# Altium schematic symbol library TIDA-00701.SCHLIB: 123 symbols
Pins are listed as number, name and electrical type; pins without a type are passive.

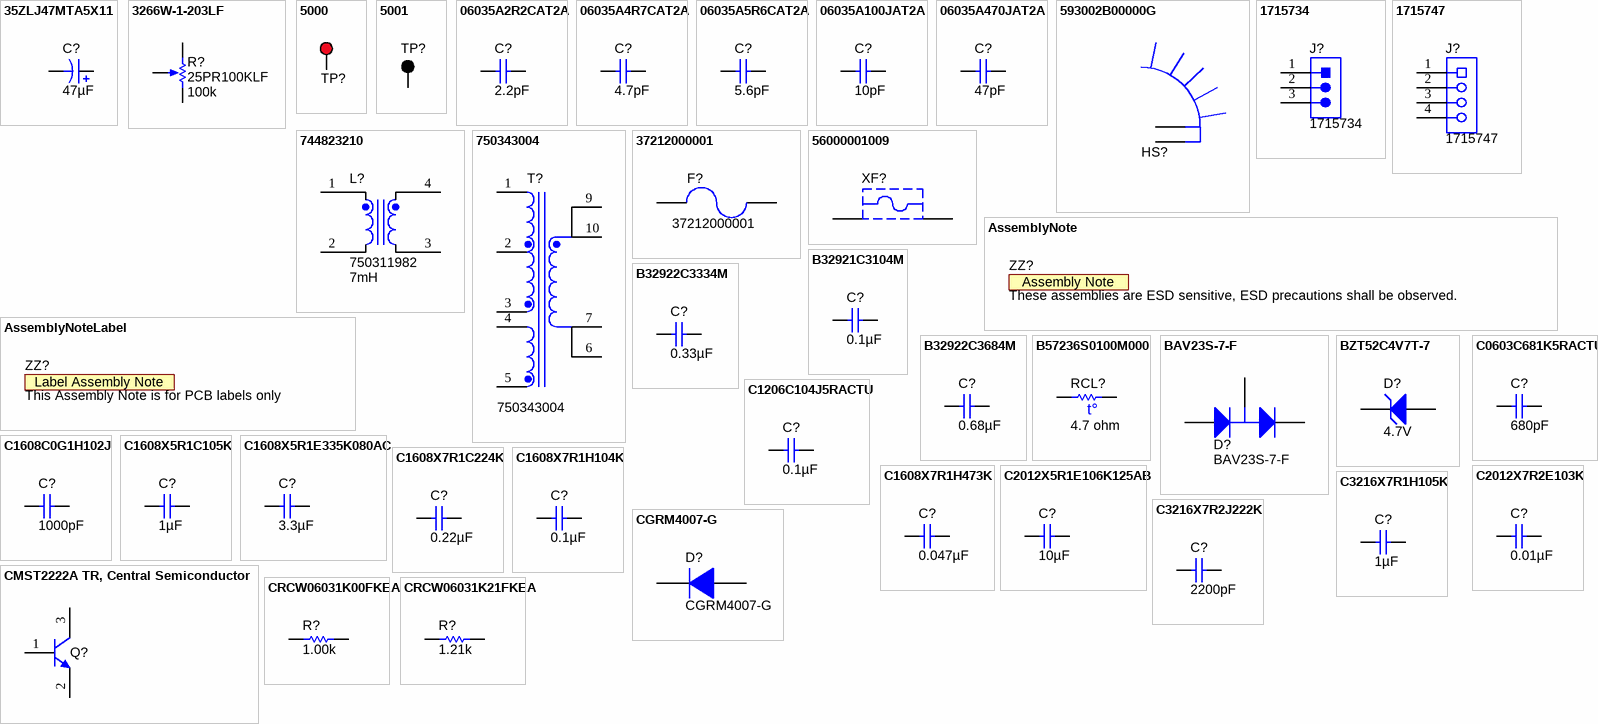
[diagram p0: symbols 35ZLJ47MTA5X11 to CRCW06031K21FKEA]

## 35ZLJ47MTA5X11
designator C?  ValueDisplayed: 47µF  (hidden comment: 35ZLJ47MTA5X11)
CAP, AL, 47 µF, 35 V, +/- 20%, 0.4 ohm, TH; Manufacturer: Rubycon; Polarized: Y; CompType: Capacitor; Value: 47uF; U/M: EA; Cap_F: 0.000047; Tolerance_%: 20; ESR_ohm: 0.4; Value1: 0.4 ohm; VDC_V: 35; Value2: 35V; IRMS_A: 0.45; TaMin_C: -40; TaMax_C: 105; Cap_Case: 5x11mm
signal-integrity model Cap
simulation model Cap
footprint ZLJ_500x1100 (TH, 2-Leads, Dia 5mm,  Lead Spacing 2mm)
pins: 1 +, 2 -

## 3266W-1-203LF
designator R?, comment 25PR100KLF  value 100k
TRIMMER 100K OHM 0.5W TH; Manufacturer: TT Electronics/BI; Sim Note: Enter the Resistance value and the set point into parameter fields.
simulation model POT (Potentiometer)
footprint TRIM_3266W
footprint POT_25PXXXXXX (Potentiometer, 25p series, through hole, 3 pin)
pins: 1 CCW, 2 WIPER, 3 CW
1 alternate drawing of the same symbol

## 5000
designator TP?  (value not drawn)
Test Point, Miniature, Red, TH; Manufacturer: Keystone; CompType: Test Point Loop; U/M: EA
footprint Keystone5000 (For Keystone 500x miniature loop terminals)
pins: 1

## 5001
designator TP?  (value not drawn)
Test Point, Miniature, Black, TH; Manufacturer: Keystone; CompType: Test Point Loop; U/M: EA
footprint Keystone5001 (For Keystone 500x miniature loop terminals)
pins: 1

## 06035A2R2CAT2A
designator C?  ValueDisplayed: 2.2pF  (hidden comment: 06035A2R2CAT2A)
CAP, CERM, 2.2 pF, 50 V, +/- 11%, C0G/NP0, 0603; Manufacturer: AVX; Polarized: N; CompType: Capacitor; Value: 2.2pF; U/M: EA; Cap_F: 0.0000000000022; Tolerance_%: 11; ESR_ohm: 1.033; Value1: 1.033 ohm; VDC_V: 50; Value2: 50V; TaMin_C: -55; TaMax_C: 125; Cap_Case: 0603
signal-integrity model Cap
simulation model Cap
footprint 0603
footprint 0603M
footprint 0603L
footprint 0603_HV
footprint 0603S
pins: 1, 2

## 06035A4R7CAT2A
designator C?  ValueDisplayed: 4.7pF  (hidden comment: 06035A4R7CAT2A)
CAP, CERM, 4.7 pF, 50 V, +/- 5%, C0G/NP0, 0603; Manufacturer: AVX; Polarized: N; CompType: Capacitor; Value: 4.7pF; U/M: EA; Cap_F: 0.0000000000047; Tolerance_%: 5; ESR_ohm: 0.633; Value1: 0.633 ohm; VDC_V: 50; Value2: 50V; TaMin_C: -55; TaMax_C: 125; Cap_Case: 0603
signal-integrity model Cap
simulation model Cap
footprint 0603
footprint 0603M
footprint 0603L
footprint 0603_HV
footprint 0603S
pins: 1, 2

## 06035A5R6CAT2A
designator C?  ValueDisplayed: 5.6pF  (hidden comment: 06035A5R6CAT2A)
CAP, CERM, 5.6 pF, 50 V, +/- 5%, C0G/NP0, 0603; Manufacturer: AVX; Polarized: N; CompType: Capacitor; Value: 5.6pF; U/M: EA; Cap_F: 0.0000000000056; Tolerance_%: 5; ESR_ohm: 0.568; Value1: 0.568 ohm; VDC_V: 50; Value2: 50V; TaMin_C: -55; TaMax_C: 125; Cap_Case: 0603
signal-integrity model Cap
simulation model Cap
footprint 0603
footprint 0603M
footprint 0603L
footprint 0603_HV
footprint 0603S
pins: 1, 2

## 06035A100JAT2A
designator C?  ValueDisplayed: 10pF  (hidden comment: 06035A100JAT2A)
CAP, CERM, 10 pF, 50 V, +/- 5%, C0G/NP0, 0603; Manufacturer: AVX; Polarized: N; CompType: Capacitor; Value: 10pF; U/M: EA; Cap_F: 0.00000000001; Tolerance_%: 5; ESR_ohm: 0.403; Value1: 0.403 ohm; VDC_V: 50; Value2: 50V; TaMin_C: -55; TaMax_C: 125; Cap_Case: 0603
signal-integrity model Cap
simulation model Cap
footprint 0603
footprint 0603M
footprint 0603L
footprint 0603_HV
footprint 0603S
pins: 1, 2

## 06035A470JAT2A
designator C?  ValueDisplayed: 47pF  (hidden comment: 06035A470JAT2A)
CAP, CERM, 47 pF, 50 V, +/- 5%, C0G/NP0, 0603; Manufacturer: AVX; Polarized: N; CompType: Capacitor; Value: 47pF; U/M: EA; Cap_F: 0.000000000047; Tolerance_%: 5; ESR_ohm: 0.174; Value1: 0.174 ohm; VDC_V: 50; Value2: 50V; TaMin_C: -55; TaMax_C: 125; Cap_Case: 0603
signal-integrity model Cap
simulation model Cap
footprint 0603
footprint 0603M
footprint 0603L
footprint 0603_HV
footprint 0603S
pins: 1, 2

## 593002B00000G
designator HS?  (value not drawn)
HEATSINK TWISTED FIN TO-220 Vertical; Manufacturer: Aavid Thermalloy; SymbolCreator: a0799628; Value: 13.4°C/W
footprint HSINK_593002B00000G (Heat Sink, TO-220 Vertical)
footprint HEATSINK_593002B03400G (HEATSINK, 25X12.7X29.97 MM)
pins: 1, 2

## 1715734
designator J?
TERM BLOCK 3POS 5.08MM, TH; Manufacturer: Phoenix Contact; SymbolCreator: a0799628; CompType: Header; U/M: EA
footprint Phoenix_1715734 (Phoenix)
pins: 1, 2, 3
3 alternate drawings of the same symbol

## 1715747
designator J?
Terminal Block, 5.08mm, 4x1, TH; Manufacturer: Phoenix Contact; SymbolCreator: a0411947; U/M: EA
footprint Phoenix_1715747 (Terminal Block, 5.08mm, 4x1, TH)
pins: 1, 2, 3, 4

## 744823210
designator L?, comment 750311982  ValueDisplayed: 7mH
Coupled inductor, 7mH, 2 A, 0.045 ohm, 3.7-7.1 mH; Manufacturer: Wurth Elektronik; SymbolCreator: a0412235; Value: 3.7-7.3mH; Ind_H: 7e-3; DCR_ohm: 0.045; Isat: 2; Tolerance_%: 30
footprint 750311982 (4 LEAD,TH)
pins: 1, 2, 3, 4

## 750343004
designator T?
TRANSFORMER, 160.0uH, 10%, TH-10PIN; Manufacturer: WURTH ELEKTRONIK; SymbolCreator: x0199378
footprint INDRD900W80D1170H1300 (INDUCTOR, 0.8MM LEAD DIA, PITCH 9MM)
footprint WE_75034300X (TRANS OR IND, PITCH 5MM, 29.84X24X33MM, TH-10PIN)
pins: 1, 2, 3, 4, 5, 6, 7, 9, 10

## 37212000001
designator F?
Fuse, 2 A, 250 V, TH; Manufacturer: Littelfuse; U/M: EA; OpeningTime_200%_max: 2; VDC_V: 250; Vdrop: 0.085; Soldering_Wave_MaxTemp_C: 260; Soldering_Wave_MaxTime_s: 5
footprint FUSE_372 (LITTELFUSE)
pins: 1, 2

## 56000001009
designator XF?  (value not drawn)
FUSE HOLDER RADIAL 250V 6.3A PCB; Manufacturer: Littelfuse; SymbolCreator: a0412235; Value: TR5
footprint FuseHolder_560000010 (Littelfuse fuse holder TR5)
pins: 1, 2

## AssemblyNote
designator ZZ?, comment These assemblies are ESD sensitive, ESD precautions shall be observed.  (no BOM)
SymbolCreator: codlsc; CompType: AssemblyNote
footprint AssemblyNote

## AssemblyNoteLabel
designator ZZ?, comment This Assembly Note is for PCB labels only  (no BOM)
SymbolCreator: a0412235
footprint AssemblyNoteLabel

## B32921C3104M
designator C?  ValueDisplayed: 0.1µF  (hidden comment: B32921C3104M)
CAP, Film, 0.1 µF, 305 V, +/- 20%, TH; Manufacturer: TDK; Polarized: N; CompType: Capacitor; Value: 0.1uF; U/M: EA; Cap_F: 0.0000001; Tolerance_%: 20; Value1: Unknown; VDC_V: 305; Value2: 305V; TaMin_C: -40; TaMax_C: 110; Cap_Case: 13x12x6mm
signal-integrity model Cap
simulation model Cap
footprint B32921_1300x1200x600 (EPCOS)
pins: 1, 2

## B32922C3334M
designator C?  ValueDisplayed: 0.33µF  (hidden comment: B32922C3334M)
CAP, Film, 0.33 µF, 630 V, +/- 20%, TH; Manufacturer: TDK; Polarized: N; CompType: Capacitor; Value: 0.33uF; U/M: EA; Cap_F: 0.00000033; Tolerance_%: 20; Value1: Unknown; VDC_V: 630; Value2: 630V; TaMax_C: 110; AEC Category: Q200
signal-integrity model Cap
simulation model Cap
footprint B32922_14.5mm
pins: 1, 2

## B32922C3684M
designator C?  ValueDisplayed: 0.68µF  (hidden comment: B32922C3684M)
CAP, Film, 0.68 µF, 630 V, +/- 20%, TH; Manufacturer: TDK; Polarized: N; CompType: Capacitor; Value: 0.68uF; U/M: EA; Cap_F: 0.00000068; Tolerance_%: 20; Value1: Unknown; VDC_V: 630; Value2: 630V; TaMax_C: 110
signal-integrity model Cap
simulation model Cap
footprint B32922_18.5mm
pins: 1, 2

## B57236S0100M000
designator RCL?, comment value 4.7 ohm  (hidden comment: B57236S479M)
ICL 4.7 OHM 20% 4.6A 11.51MM; Manufacturer: TDK; CompType: ThermistorNTC; Tolerance_%: 20; Power_W: 2.1; U/M: EA; TaMin_C: -55; TaMax_C: 170
footprint THERM_B57236S0 (EPCOS)
pins: 1, 2

## BAV23S-7-F
designator D?
Diode, Switching, 200 V, 0.4 A, SOT-23; Manufacturer: Diodes Inc.; U/M: EA; Vf_V: 1.25; Value: 200V; Value1: 0.4A; Value2: 1.25V; Io_A: 0.4; Vr_V: 200; TJmax_C: 150; RJC_CperW: 357
footprint SOT-23 (SOT23, 3-Leads, Body 2.9x1.3mm, Pitch 0.95mm, Lead Span 2.5mm, IPC Medium Density)
footprint SOT-23M
footprint SOT-23L
pins: 1 A, 2 K, 3 C
1 alternate drawing of the same symbol

## BZT52C4V7T-7
designator D?  value 4.7V  (hidden comment: BZT52C4V7T-7)
Diode, Zener, 4.7 V, 300 mW, SOD-523; Manufacturer: Diodes Inc.; U/M: EA; SymbolCreator: a0412235; Power_W: 0.3; Vz_V: 4.7; Value1: 0.3W; RJA_CperW: 417
signal-integrity model Diode
footprint SOD-523
pins: 1 K, 2 A

## C0603C681K5RACTU
designator C?  ValueDisplayed: 680pF  (hidden comment: C0603C681K5RACTU)
CAP, CERM, 680 pF, 50 V, +/- 10%, X7R, 0603; Manufacturer: Kemet; Polarized: N; CompType: Capacitor; Value: 680pF; U/M: EA; Cap_F: 0.00000000068; Tolerance_%: 10; Value1: Unknown; VDC_V: 50; Value2: 50V; TaMin_C: -55; TaMax_C: 125; Cap_Case: 0603
signal-integrity model Cap
simulation model Cap
footprint 0603
footprint 0603M
footprint 0603L
footprint 0603_HV
footprint 0603S
pins: 1, 2

## C1206C104J5RACTU
designator C?  ValueDisplayed: 0.1µF  (hidden comment: C1206C104J5RACTU)
CAP, CERM, 0.1 µF, 50 V, +/- 5%, X7R, 1206; Manufacturer: Kemet; Polarized: N; CompType: Capacitor; Value: 0.1uF; U/M: EA; Cap_F: 0.0000001; Tolerance_%: 5; ESR_ohm: 0.059; Value1: 0.059 ohm; VDC_V: 50; Value2: 50V; IRMS_A: 1.2; TaMin_C: -55; TaMax_C: 125; Cap_Case: 1206
signal-integrity model Cap
simulation model Cap
footprint 1206
footprint 1206M
footprint 1206L
pins: 1, 2

## C1608C0G1H102J
designator C?  ValueDisplayed: 1000pF  (hidden comment: C1608C0G1H102J)
CAP, CERM, 1000 pF, 50 V, +/- 5%, C0G/NP0, 0603; Manufacturer: TDK; Polarized: N; CompType: Capacitor; Value: 1000pF; U/M: EA; Cap_F: 0.000000001; Tolerance_%: 5; ESR_ohm: 0.0563; Value1: 0.0563 ohm; VDC_V: 50; Value2: 50V; TaMin_C: -55; TaMax_C: 125; Cap_Case: 0603
signal-integrity model Cap
simulation model Cap
footprint 0603
footprint 0603M
footprint 0603L
footprint 0603_HV
footprint 0603S
pins: 1, 2

## C1608X5R1C105K
designator C?  ValueDisplayed: 1µF  (hidden comment: C1608X5R1C105K)
CAP, CERM, 1 µF, 16 V, +/- 10%, X5R, 0603; Manufacturer: TDK; Polarized: N; CompType: Capacitor; Value: 1uF; U/M: EA; Cap_F: 0.000001; Tolerance_%: 10; ESR_ohm: 0.0057; Value1: 0.0057 ohm; VDC_V: 16; Value2: 16V; TaMin_C: -55; TaMax_C: 85; Cap_Case: 0603; AEC Category: Q200
signal-integrity model Cap
simulation model Cap
footprint 0603
footprint 0603M
footprint 0603L
footprint 0603_HV
footprint 0603S
pins: 1, 2

## C1608X5R1E335K080AC
designator C?  ValueDisplayed: 3.3µF  (hidden comment: C1608X5R1E335K080AC)
CAP, CERM, 3.3 µF, 25 V, +/- 10%, X5R, 0603; Manufacturer: TDK; Polarized: N; CompType: Capacitor; Value: 3.3uF; U/M: EA; Cap_F: 0.0000033; Tolerance_%: 10; Value1: Unknown; VDC_V: 25; Value2: 25V; TaMin_C: -55; TaMax_C: 85; Cap_Case: 0603
signal-integrity model Cap
simulation model Cap
footprint 0603
footprint 0603M
footprint 0603L
footprint 0603_HV
footprint 0603S
pins: 1, 2

## C1608X7R1C224K
designator C?  ValueDisplayed: 0.22µF  (hidden comment: C1608X7R1C224K)
CAP, CERM, 0.22 µF, 16 V, +/- 10%, X7R, 0603; Manufacturer: TDK; Polarized: N; CompType: Capacitor; Value: 0.22uF; U/M: EA; Cap_F: 0.00000022; Tolerance_%: 10; ESR_ohm: 0.0125; Value1: 0.0125 ohm; VDC_V: 16; Value2: 16V; TaMin_C: -55; TaMax_C: 125; Cap_Case: 0603
signal-integrity model Cap
simulation model Cap
footprint 0603
footprint 0603M
footprint 0603L
footprint 0603_HV
footprint 0603S
pins: 1, 2

## C1608X7R1H104K
designator C?  ValueDisplayed: 0.1µF  (hidden comment: C1608X7R1H104K)
CAP, CERM, 0.1 µF, 50 V, +/- 10%, X7R, 0603; Manufacturer: TDK; Polarized: N; CompType: Capacitor; Value: 0.1uF; U/M: EA; Cap_F: 0.0000001; Tolerance_%: 10; ESR_ohm: 0.017; Value1: 0.017 ohm; VDC_V: 50; Value2: 50V; TaMin_C: -55; TaMax_C: 125; Cap_Case: 0603
signal-integrity model Cap
simulation model Cap
footprint 0603
footprint 0603M
footprint 0603L
footprint 0603_HV
footprint 0603S
pins: 1, 2

## C1608X7R1H473K
designator C?  ValueDisplayed: 0.047µF  (hidden comment: C1608X7R1H473K)
CAP, CERM, 0.047 µF, 50 V, +/- 10%, X7R, 0603; Manufacturer: TDK; Polarized: N; CompType: Capacitor; Value: 0.047uF; U/M: EA; Cap_F: 0.000000047; Tolerance_%: 10; ESR_ohm: 0.0234; Value1: 0.0234 ohm; VDC_V: 50; Value2: 50V; TaMin_C: -55; TaMax_C: 125; Cap_Case: 0603
signal-integrity model Cap
simulation model Cap
footprint 0603
footprint 0603M
footprint 0603L
footprint 0603_HV
footprint 0603S
pins: 1, 2

## C2012X5R1E106K125AB
designator C?  ValueDisplayed: 10µF  (hidden comment: C2012X5R1E106K125AB)
CAP, CERM, 10 µF, 25 V, +/- 10%, X5R, 0805; Manufacturer: TDK; Polarized: N; CompType: Capacitor; Value: 10uF; U/M: EA; Cap_F: 0.00001; Tolerance_%: 10; Value1: Unknown; VDC_V: 25; Value2: 25V; TaMin_C: -55; TaMax_C: 85; Cap_Case: 0805
signal-integrity model Cap
simulation model Cap
footprint 0805_HV (0805 with 30mil clearance between pads)
footprint 0805
footprint 0805M
footprint 0805L
pins: 1, 2

## C2012X7R2E103K
designator C?  ValueDisplayed: 0.01µF  (hidden comment: C2012X7R2E103K)
CAP, CERM, 0.01 µF, 250 V, +/- 10%, X7R, 0805; Manufacturer: TDK; Polarized: N; CompType: Capacitor; Value: 0.01uF; U/M: EA; Cap_F: 0.00000001; Tolerance_%: 10; ESR_ohm: 0.0681; Value1: 0.0681 ohm; VDC_V: 250; Value2: 250V; TaMin_C: -55; TaMax_C: 125; Cap_Case: 0805
signal-integrity model Cap
simulation model Cap
footprint 0805_HV
footprint 0805
footprint 0805M
footprint 0805L
pins: 1, 2

## C3216X7R1H105K
designator C?  ValueDisplayed: 1µF  (hidden comment: C3216X7R1H105K)
CAP, CERM, 1 µF, 50 V, +/- 10%, X7R, 1206; Manufacturer: TDK; Polarized: N; CompType: Capacitor; Value: 1uF; U/M: EA; Cap_F: 0.000001; Tolerance_%: 10; ESR_ohm: 0.01; Value1: 0.01 ohm; VDC_V: 50; Value2: 50V; IRMS_A: 3.2; TaMin_C: -55; TaMax_C: 125; Cap_Case: 1206
signal-integrity model Cap
simulation model Cap
footprint 1206
footprint 1206M
footprint 1206L
pins: 1, 2

## C3216X7R2J222K
designator C?  ValueDisplayed: 2200pF  (hidden comment: C3216X7R2J222K)
CAP, CERM, 2200 pF, 630 V, +/- 10%, X7R, 1206; Manufacturer: TDK; Polarized: N; CompType: Capacitor; Value: 2200pF; U/M: EA; Cap_F: 0.0000000022; Tolerance_%: 10; ESR_ohm: 0.151; Value1: 0.151 ohm; VDC_V: 630; Value2: 630V; TaMin_C: -55; TaMax_C: 125; Cap_Case: 1206; AEC Category: Q200
signal-integrity model Cap
simulation model Cap
footprint 1206
footprint 1206M
footprint 1206L
pins: 1, 2

## CGRM4007-G
designator D?
Diode, P-N, 1000 V, 1 A, 3.9x1.7x1.8mm; Manufacturer: Comchip Technology; U/M: EA; Vf_V: 1.1; Value: 1000V; Value1: 1A; Value2: 1.1V; Io_A: 1; Vr_V: 1000; TJmax_C: 150
signal-integrity model Diode
footprint MINI-SMA
pins: 1 K, 2 A

## CMST2222A TR, Central Semiconductor
designator Q?, comment MMBT4401WT1G  (value not drawn)
Transistor, NPN, 40 V, 0.6 A, SOT-323; Manufacturer: ON Semiconductor; CompType: BJT; PNP: 0; NPN: 1; Vceo_V: 40; Vcesat1_V: 0.3; Value: 40 V; IcRated_A: 0.6; Value1: 0.6 A; TaMin_C: -65; TaMax_C: 150; U/M: EA
footprint SOT-323 (Zetex recommended land pattern.  March 2007)
pins: 1 B, 2 E, 3 C

## CRCW06031K00FKEA
designator R?  ValueDisplayed: 1.00k  (hidden comment: CRCW06031K00FKEA)
RES, 1.00 k, 1%, 0.1 W, 0603; Manufacturer: Vishay-Dale; CompType: Resistor; Value: 1.00k; Res_ohm: 1000; Value_Code: 1k00; Tolerance_%: 1; Power_W: 0.1; Value2: 0.1W; VDC_V: 75; TempCo: 100 ppm/C; EIA_Code: E96; U/M: EA
signal-integrity model Resistor
simulation model Resistor
footprint 0603
footprint 0603M
footprint 0603L
footprint 0603_HV
footprint 0603S
pins: 1, 2

## CRCW06031K21FKEA
designator R?  ValueDisplayed: 1.21k  (hidden comment: CRCW06031K21FKEA)
RES, 1.21 k, 1%, 0.1 W, 0603; Manufacturer: Vishay-Dale; CompType: Resistor; Value: 1.21k; Res_ohm: 1210; Value_Code: 1k21; Tolerance_%: 1; Power_W: 0.1; Value2: 0.1W; VDC_V: 75; TempCo: 100 ppm/C; EIA_Code: E96; U/M: EA; AEC Category: Q200
signal-integrity model Resistor
simulation model Resistor
footprint 0603
footprint 0603M
footprint 0603L
footprint 0603_HV
footprint 0603S
pins: 1, 2

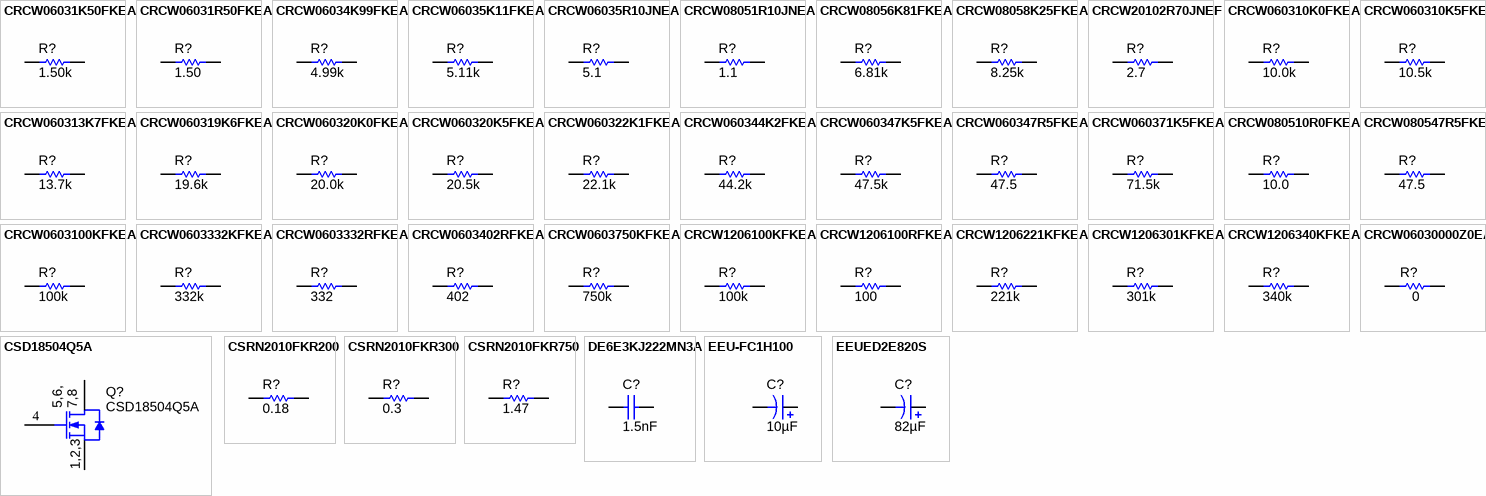
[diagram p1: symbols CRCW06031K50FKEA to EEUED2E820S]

## CRCW06031K50FKEA
designator R?  ValueDisplayed: 1.50k  (hidden comment: CRCW06031K50FKEA)
RES, 1.50 k, 1%, 0.1 W, 0603; Manufacturer: Vishay-Dale; CompType: Resistor; Value: 1.50k; Res_ohm: 1500; Value_Code: 1k50; Tolerance_%: 1; Power_W: 0.1; Value2: 0.1W; VDC_V: 75; TempCo: 100 ppm/C; EIA_Code: E96; U/M: EA
signal-integrity model Resistor
simulation model Resistor
footprint 0603
footprint 0603M
footprint 0603L
footprint 0603_HV
footprint 0603S
pins: 1, 2

## CRCW06031R50FKEA
designator R?  ValueDisplayed: 1.50  (hidden comment: CRCW06031R50FKEA)
RES, 1.50, 1%, 0.1 W, 0603; Manufacturer: Vishay-Dale; CompType: Resistor; Value: 1.50; Res_ohm: 1.5; Value_Code: 1R50; Tolerance_%: 1; Power_W: 0.1; Value2: 0.1W; VDC_V: 75; TempCo: 100 ppm/C; EIA_Code: E96; U/M: EA
signal-integrity model Resistor
simulation model Resistor
footprint 0603
footprint 0603M
footprint 0603L
footprint 0603_HV
footprint 0603S
pins: 1, 2

## CRCW06034K99FKEA
designator R?  ValueDisplayed: 4.99k  (hidden comment: CRCW06034K99FKEA)
RES, 4.99 k, 1%, 0.1 W, 0603; Manufacturer: Vishay-Dale; CompType: Resistor; Value: 4.99k; Res_ohm: 4990; Value_Code: 4k99; Tolerance_%: 1; Power_W: 0.1; Value2: 0.1W; VDC_V: 75; TempCo: 100 ppm/C; EIA_Code: E96; U/M: EA
signal-integrity model Resistor
simulation model Resistor
footprint 0603
footprint 0603M
footprint 0603L
footprint 0603_HV
footprint 0603S
pins: 1, 2

## CRCW06035K11FKEA
designator R?  ValueDisplayed: 5.11k  (hidden comment: CRCW06035K11FKEA)
RES, 5.11 k, 1%, 0.1 W, 0603; Manufacturer: Vishay-Dale; CompType: Resistor; Value: 5.11k; Res_ohm: 5110; Value_Code: 5k11; Tolerance_%: 1; Power_W: 0.1; Value2: 0.1W; VDC_V: 75; TempCo: 100 ppm/C; EIA_Code: E96; U/M: EA
signal-integrity model Resistor
simulation model Resistor
footprint 0603
footprint 0603M
footprint 0603L
footprint 0603_HV
footprint 0603S
pins: 1, 2

## CRCW06035R10JNEA
designator R?  ValueDisplayed: 5.1  (hidden comment: CRCW06035R10JNEA)
RES, 5.1, 5%, 0.1 W, 0603; Manufacturer: Vishay-Dale; CompType: Resistor; Value: 5.1; Value_Code: 5R10; Tolerance_%: 5; Power_W: 0.1; Value2: 0.1W; VDC_V: 75; TempCo: 200 ppm/C; EIA_Code: E24; U/M: EA; AEC Category: Q200
signal-integrity model Resistor
simulation model Resistor
footprint 0603
footprint 0603M
footprint 0603L
footprint 0603_HV
footprint 0603S
pins: 1, 2

## CRCW08051R10JNEA
designator R?  ValueDisplayed: 1.1  (hidden comment: CRCW08051R10JNEA)
RES, 1.1, 5%, 0.125 W, 0805; Manufacturer: Vishay-Dale; CompType: Resistor; Value: 1.1; Value_Code: 1R10; Tolerance_%: 5; Power_W: 0.125; Value2: 0.125W; VDC_V: 150; TempCo: 200 ppm/C; EIA_Code: E24; U/M: EA; AEC Category: Q200
signal-integrity model Resistor
simulation model Resistor
footprint 0805_HV
footprint 0805_HV1
footprint 0805
footprint 0805M
pins: 1, 2

## CRCW08056K81FKEA
designator R?  ValueDisplayed: 6.81k  (hidden comment: CRCW08056K81FKEA)
RES, 6.81 k, 1%, 0.125 W, 0805; Manufacturer: Vishay-Dale; CompType: Resistor; Value: 6.81k; Res_ohm: 6810; Value_Code: 6k81; Tolerance_%: 1; Power_W: 0.125; Value2: 0.125W; VDC_V: 150; TempCo: 100 ppm/C; EIA_Code: E96; U/M: EA; AEC Category: Q200
signal-integrity model Resistor
simulation model Resistor
footprint 0805_HV
footprint 0805_HV1
footprint 0805
footprint 0805M
pins: 1, 2

## CRCW08058K25FKEA
designator R?  ValueDisplayed: 8.25k  (hidden comment: CRCW08058K25FKEA)
RES, 8.25 k, 1%, 0.125 W, 0805; Manufacturer: Vishay-Dale; CompType: Resistor; Value: 8.25k; Res_ohm: 8250; Value_Code: 8k25; Tolerance_%: 1; Power_W: 0.125; Value2: 0.125W; VDC_V: 150; TempCo: 100 ppm/C; EIA_Code: E96; U/M: EA; AEC Category: Q200
signal-integrity model Resistor
simulation model Resistor
footprint 0805_HV
footprint 0805_HV1
footprint 0805
footprint 0805M
pins: 1, 2

## CRCW20102R70JNEF
designator R?  ValueDisplayed: 2.7  (hidden comment: CRCW20102R70JNEF)
RES, 2.7, 5%, 0.75 W, 2010; Manufacturer: Vishay-Dale; CompType: Resistor; Value: 2.7; Value_Code: 2R70; Tolerance_%: 5; Power_W: 0.75; Value2: 0.75W; VDC_V: 400; TempCo: 200 ppm/C; EIA_Code: E24; U/M: EA
signal-integrity model Resistor
simulation model Resistor
footprint 2010
footprint 2010M
footprint 2010L
pins: 1, 2

## CRCW060310K0FKEA
designator R?  ValueDisplayed: 10.0k  (hidden comment: CRCW060310K0FKEA)
RES, 10.0 k, 1%, 0.1 W, 0603; Manufacturer: Vishay-Dale; CompType: Resistor; Value: 10.0k; Res_ohm: 10000; Value_Code: 10k0; Tolerance_%: 1; Power_W: 0.1; Value2: 0.1W; VDC_V: 75; TempCo: 100 ppm/C; EIA_Code: E96; U/M: EA
signal-integrity model Resistor
simulation model Resistor
footprint 0603
footprint 0603M
footprint 0603L
footprint 0603_HV
footprint 0603S
pins: 1, 2

## CRCW060310K5FKEA
designator R?  ValueDisplayed: 10.5k  (hidden comment: CRCW060310K5FKEA)
RES, 10.5 k, 1%, 0.1 W, 0603; Manufacturer: Vishay-Dale; CompType: Resistor; Value: 10.5k; Res_ohm: 10500; Value_Code: 10k5; Tolerance_%: 1; Power_W: 0.1; Value2: 0.1W; VDC_V: 75; TempCo: 100 ppm/C; EIA_Code: E96; U/M: EA; AEC Category: Q200
signal-integrity model Resistor
simulation model Resistor
footprint 0603
footprint 0603M
footprint 0603L
footprint 0603_HV
footprint 0603S
pins: 1, 2

## CRCW060313K7FKEA
designator R?  ValueDisplayed: 13.7k  (hidden comment: CRCW060313K7FKEA)
RES, 13.7 k, 1%, 0.1 W, 0603; Manufacturer: Vishay-Dale; CompType: Resistor; Value: 13.7k; Res_ohm: 13700; Value_Code: 13k7; Tolerance_%: 1; Power_W: 0.1; Value2: 0.1W; VDC_V: 75; TempCo: 100 ppm/C; EIA_Code: E96; U/M: EA
signal-integrity model Resistor
simulation model Resistor
footprint 0603
footprint 0603M
footprint 0603L
footprint 0603_HV
footprint 0603S
pins: 1, 2

## CRCW060319K6FKEA
designator R?  ValueDisplayed: 19.6k  (hidden comment: CRCW060319K6FKEA)
RES, 19.6 k, 1%, 0.1 W, 0603; Manufacturer: Vishay-Dale; CompType: Resistor; Value: 19.6k; Res_ohm: 19600; Value_Code: 19k6; Tolerance_%: 1; Power_W: 0.1; Value2: 0.1W; VDC_V: 75; TempCo: 100 ppm/C; EIA_Code: E96; U/M: EA
signal-integrity model Resistor
simulation model Resistor
footprint 0603
footprint 0603M
footprint 0603L
footprint 0603_HV
footprint 0603S
pins: 1, 2

## CRCW060320K0FKEA
designator R?  ValueDisplayed: 20.0k  (hidden comment: CRCW060320K0FKEA)
RES, 20.0 k, 1%, 0.1 W, 0603; Manufacturer: Vishay-Dale; CompType: Resistor; Value: 20.0k; Res_ohm: 20000; Value_Code: 20k0; Tolerance_%: 1; Power_W: 0.1; Value2: 0.1W; VDC_V: 75; TempCo: 100 ppm/C; EIA_Code: E96; U/M: EA
signal-integrity model Resistor
simulation model Resistor
footprint 0603
footprint 0603M
footprint 0603L
footprint 0603_HV
footprint 0603S
pins: 1, 2

## CRCW060320K5FKEA
designator R?  ValueDisplayed: 20.5k  (hidden comment: CRCW060320K5FKEA)
RES, 20.5 k, 1%, 0.1 W, 0603; Manufacturer: Vishay-Dale; CompType: Resistor; Value: 20.5k; Res_ohm: 20500; Value_Code: 20k5; Tolerance_%: 1; Power_W: 0.1; Value2: 0.1W; VDC_V: 75; TempCo: 100 ppm/C; EIA_Code: E96; U/M: EA
signal-integrity model Resistor
simulation model Resistor
footprint 0603
footprint 0603M
footprint 0603L
footprint 0603_HV
footprint 0603S
pins: 1, 2

## CRCW060322K1FKEA
designator R?  ValueDisplayed: 22.1k  (hidden comment: CRCW060322K1FKEA)
RES, 22.1 k, 1%, 0.1 W, 0603; Manufacturer: Vishay-Dale; CompType: Resistor; Value: 22.1k; Res_ohm: 22100; Value_Code: 22k1; Tolerance_%: 1; Power_W: 0.1; Value2: 0.1W; VDC_V: 75; TempCo: 100 ppm/C; EIA_Code: E96; U/M: EA
signal-integrity model Resistor
simulation model Resistor
footprint 0603
footprint 0603M
footprint 0603L
footprint 0603_HV
footprint 0603S
pins: 1, 2

## CRCW060344K2FKEA
designator R?  ValueDisplayed: 44.2k  (hidden comment: CRCW060344K2FKEA)
RES, 44.2 k, 1%, 0.1 W, 0603; Manufacturer: Vishay-Dale; CompType: Resistor; Value: 44.2k; Res_ohm: 44200; Value_Code: 44k2; Tolerance_%: 1; Power_W: 0.1; Value2: 0.1W; VDC_V: 75; TempCo: 100 ppm/C; EIA_Code: E96; U/M: EA
signal-integrity model Resistor
simulation model Resistor
footprint 0603
footprint 0603M
footprint 0603L
footprint 0603_HV
footprint 0603S
pins: 1, 2

## CRCW060347K5FKEA
designator R?  ValueDisplayed: 47.5k  (hidden comment: CRCW060347K5FKEA)
RES, 47.5 k, 1%, 0.1 W, 0603; Manufacturer: Vishay-Dale; CompType: Resistor; Value: 47.5k; Res_ohm: 47500; Value_Code: 47k5; Tolerance_%: 1; Power_W: 0.1; Value2: 0.1W; VDC_V: 75; TempCo: 100 ppm/C; EIA_Code: E96; U/M: EA
signal-integrity model Resistor
simulation model Resistor
footprint 0603
footprint 0603M
footprint 0603L
footprint 0603_HV
footprint 0603S
pins: 1, 2

## CRCW060347R5FKEA
designator R?  ValueDisplayed: 47.5  (hidden comment: CRCW060347R5FKEA)
RES, 47.5, 1%, 0.1 W, 0603; Manufacturer: Vishay-Dale; CompType: Resistor; Value: 47.5; Value_Code: 47R5; Tolerance_%: 1; Power_W: 0.1; Value2: 0.1W; VDC_V: 75; TempCo: 100 ppm/C; EIA_Code: E96; U/M: EA
signal-integrity model Resistor
simulation model Resistor
footprint 0603
footprint 0603M
footprint 0603L
footprint 0603_HV
footprint 0603S
pins: 1, 2

## CRCW060371K5FKEA
designator R?  ValueDisplayed: 71.5k  (hidden comment: CRCW060371K5FKEA)
RES, 71.5 k, 1%, 0.1 W, 0603; Manufacturer: Vishay-Dale; CompType: Resistor; Value: 71.5k; Res_ohm: 71500; Value_Code: 71k5; Tolerance_%: 1; Power_W: 0.1; Value2: 0.1W; VDC_V: 75; TempCo: 100 ppm/C; EIA_Code: E96; U/M: EA
signal-integrity model Resistor
simulation model Resistor
footprint 0603
footprint 0603M
footprint 0603L
footprint 0603_HV
footprint 0603S
pins: 1, 2

## CRCW080510R0FKEA
designator R?  ValueDisplayed: 10.0  (hidden comment: CRCW080510R0FKEA)
RES, 10.0, 1%, 0.125 W, 0805; Manufacturer: Vishay-Dale; CompType: Resistor; Value: 10.0; Res_ohm: 10; Value_Code: 10R0; Tolerance_%: 1; Power_W: 0.125; Value2: 0.125W; VDC_V: 150; TempCo: 100 ppm/C; EIA_Code: E96; U/M: EA
signal-integrity model Resistor
simulation model Resistor
footprint 0805_HV
footprint 0805
footprint 0805M
footprint 0805L
pins: 1, 2

## CRCW080547R5FKEA
designator R?  ValueDisplayed: 47.5  (hidden comment: CRCW080547R5FKEA)
RES, 47.5, 1%, 0.125 W, 0805; Manufacturer: Vishay-Dale; CompType: Resistor; Value: 47.5; Value_Code: 47R5; Tolerance_%: 1; Power_W: 0.125; Value2: 0.125W; VDC_V: 150; TempCo: 100 ppm/C; EIA_Code: E96; U/M: EA
signal-integrity model Resistor
simulation model Resistor
footprint 0805_HV
footprint 0805
footprint 0805M
footprint 0805L
pins: 1, 2

## CRCW0603100KFKEA
designator R?  ValueDisplayed: 100k  (hidden comment: CRCW0603100KFKEA)
RES, 100 k, 1%, 0.1 W, 0603; Manufacturer: Vishay-Dale; CompType: Resistor; Value: 100k; Res_ohm: 100000; Tolerance_%: 1; Power_W: 0.1; Value2: 0.1W; VDC_V: 75; TempCo: 100 ppm/C; EIA_Code: E96; U/M: EA
signal-integrity model Resistor
simulation model Resistor
footprint 0603
footprint 0603M
footprint 0603L
footprint 0603_HV
footprint 0603S
pins: 1, 2

## CRCW0603332KFKEA
designator R?  ValueDisplayed: 332k  (hidden comment: CRCW0603332KFKEA)
RES, 332 k, 1%, 0.1 W, 0603; Manufacturer: Vishay-Dale; CompType: Resistor; Value: 332k; Res_ohm: 332000; Tolerance_%: 1; Power_W: 0.1; Value2: 0.1W; VDC_V: 75; TempCo: 100 ppm/C; EIA_Code: E96; U/M: EA
signal-integrity model Resistor
simulation model Resistor
footprint 0603
footprint 0603M
footprint 0603L
footprint 0603_HV
footprint 0603S
pins: 1, 2

## CRCW0603332RFKEA
designator R?  ValueDisplayed: 332  (hidden comment: CRCW0603332RFKEA)
RES, 332, 1%, 0.1 W, 0603; Manufacturer: Vishay-Dale; CompType: Resistor; Value: 332; Value_Code: 332R; Tolerance_%: 1; Power_W: 0.1; Value2: 0.1W; VDC_V: 75; TempCo: 100 ppm/C; EIA_Code: E96; U/M: EA
signal-integrity model Resistor
simulation model Resistor
footprint 0603
footprint 0603M
footprint 0603L
footprint 0603_HV
footprint 0603S
pins: 1, 2

## CRCW0603402RFKEA
designator R?  ValueDisplayed: 402  (hidden comment: CRCW0603402RFKEA)
RES, 402, 1%, 0.1 W, 0603; Manufacturer: Vishay-Dale; CompType: Resistor; Value: 402; Value_Code: 402R; Tolerance_%: 1; Power_W: 0.1; Value2: 0.1W; VDC_V: 75; TempCo: 100 ppm/C; EIA_Code: E96; U/M: EA
signal-integrity model Resistor
simulation model Resistor
footprint 0603
footprint 0603M
footprint 0603L
footprint 0603_HV
footprint 0603S
pins: 1, 2

## CRCW0603750KFKEA
designator R?  ValueDisplayed: 750k  (hidden comment: CRCW0603750KFKEA)
RES, 750 k, 1%, 0.1 W, 0603; Manufacturer: Vishay-Dale; CompType: Resistor; Value: 750k; Res_ohm: 750000; Tolerance_%: 1; Power_W: 0.1; Value2: 0.1W; VDC_V: 75; TempCo: 100 ppm/C; EIA_Code: E96; U/M: EA
signal-integrity model Resistor
simulation model Resistor
footprint 0603
footprint 0603M
footprint 0603L
footprint 0603_HV
footprint 0603S
pins: 1, 2

## CRCW1206100KFKEA
designator R?  ValueDisplayed: 100k  (hidden comment: CRCW1206100KFKEA)
RES, 100 k, 1%, 0.25 W, 1206; Manufacturer: Vishay-Dale; CompType: Resistor; Value: 100k; Res_ohm: 100000; Tolerance_%: 1; Power_W: 0.25; Value2: 0.25W; VDC_V: 200; TempCo: 100 ppm/C; EIA_Code: E96; U/M: EA
signal-integrity model Resistor
simulation model Resistor
footprint 1206
footprint 1206M
footprint 1206L
pins: 1, 2

## CRCW1206100RFKEA
designator R?  ValueDisplayed: 100  (hidden comment: CRCW1206100RFKEA)
RES, 100, 1%, 0.25 W, 1206; Manufacturer: Vishay-Dale; CompType: Resistor; Value: 100; Value_Code: 100R; Tolerance_%: 1; Power_W: 0.25; Value2: 0.25W; VDC_V: 200; TempCo: 100 ppm/C; EIA_Code: E96; U/M: EA
signal-integrity model Resistor
simulation model Resistor
footprint 1206
footprint 1206M
footprint 1206L
pins: 1, 2

## CRCW1206221KFKEA
designator R?  ValueDisplayed: 221k  (hidden comment: CRCW1206221KFKEA)
RES, 221 k, 1%, 0.25 W, 1206; Manufacturer: Vishay-Dale; Value: 221k; CompType: Resistor; Res_ohm: 221000; Tolerance_%: 1; Power_W: 0.25; Value2: 0.25W; VDC_V: 200; TempCo: 100 ppm/C; EIA_Code: E96; U/M: EA
signal-integrity model Resistor
simulation model Resistor
footprint 1206
footprint 1206M
footprint 1206L
pins: 1, 2

## CRCW1206301KFKEA
designator R?  ValueDisplayed: 301k  (hidden comment: CRCW1206301KFKEA)
RES, 301 k, 1%, 0.25 W, 1206; Manufacturer: Vishay-Dale; CompType: Resistor; Value: 301k; Res_ohm: 301000; Tolerance_%: 1; Power_W: 0.25; Value2: 0.25W; VDC_V: 200; TempCo: 100 ppm/C; EIA_Code: E96; U/M: EA; AEC Category: Q200
signal-integrity model Resistor
simulation model Resistor
footprint 1206
footprint 1206M
footprint 1206L
pins: 1, 2

## CRCW1206340KFKEA
designator R?  ValueDisplayed: 340k  (hidden comment: CRCW1206340KFKEA)
RES, 340 k, 1%, 0.25 W, 1206; Manufacturer: Vishay-Dale; Value: 340k; CompType: Resistor; Res_ohm: 340000; Tolerance_%: 1; Power_W: 0.25; Value2: 0.25W; VDC_V: 200; TempCo: 100 ppm/C; EIA_Code: E96; U/M: EA
signal-integrity model Resistor
simulation model Resistor
footprint 1206 (1206 from SM-752 data)
footprint 1206M
footprint 1206L
pins: 1, 2

## CRCW06030000Z0EA
designator R?  ValueDisplayed: 0  (hidden comment: CRCW06030000Z0EA)
RES, 0, 5%, 0.1 W, 0603; Manufacturer: Vishay-Dale; CompType: Resistor; Value: 0; Value_Code: 0000; Tolerance_%: 5; Power_W: 0.1; Value2: 0.1W; VDC_V: 75; TempCo: 200 ppm/C; EIA_Code: E24; U/M: EA; AEC Category: Q200
signal-integrity model Resistor
simulation model Resistor
footprint 0603
footprint 0603M
footprint 0603L
footprint 0603_HV
footprint 0603S
pins: 1, 2

## CSD18504Q5A
designator Q?
MOSFET, N-CH, 40 V, 15 A, SON 5x6mm; Manufacturer: Texas Instruments; Alternate Manufacturer: None; U/M: EA; ChType: N; Value: 40V; VdsMax_V: 40; Value1: 0.0098 ohm; Rdson45_ohm: 0.0098; Value2: 7.7 nC; QgTyp_nC: 7.7; Vgs_V: 20; IdsMax_A: 15
footprint TRANS_NexFET_Q5A
pins: 1 S, 2 S, 3 S, 4 G, 5 D, 6 D, 7 D, 8 D, 9 D

## CSRN2010FKR200
designator R?, comment ValueDisplayed: 0.18  (hidden comment: MCR50JZHFLR180)
RES SMD 0.18 OHM 1% 1/2W 2010; Manufacturer: Rohm Semiconductor; CompType: Resistor; Value: 0.18; Res_ohm: 0.2; Value_Code: R200; Tolerance_%: 1; Value2: 0.5W; TempCo: 250 ppm/C; U/M: EA; AEC Category: Q200
signal-integrity model Resistor
simulation model Resistor
footprint 2010
footprint 2010M
footprint 2010L
pins: 1, 2

## CSRN2010FKR300
designator R?  ValueDisplayed: 0.3  (hidden comment: CSRN2010FKR300)
RES, 0.3, 1%, 1 W, 2010; Manufacturer: Stackpole Electronics Inc; CompType: Resistor; Value: 0.3; Value_Code: R300; Tolerance_%: 1; Value2: 1W; TempCo: 250 ppm/C; EIA_Code: E96; U/M: EA; AEC Category: Q200
signal-integrity model Resistor
simulation model Resistor
footprint 2010
footprint 2010M
footprint 2010L
pins: 1, 2

## CSRN2010FKR750
designator R?, comment ValueDisplayed: 1.47  (hidden comment: RMCF2010FT1R47)
RES SMD 1.47 OHM 1% 3/4W 2010; Manufacturer: Stackpole Electronics Inc; CompType: Resistor; Value: 1.47; Res_ohm: 0.75; Tolerance_%: 1; Value2: 0.75W; TempCo: 250 ppm/C; EIA_Code: E96; U/M: EA; AEC Category: Q200
signal-integrity model Resistor
simulation model Resistor
footprint 2010
footprint 2010M
footprint 2010L
pins: 1, 2

## DE6E3KJ222MN3A
designator C?, comment ValueDisplayed: 1.5nF  (hidden comment: CS75ZU2GA152MYNKA)
CAP CER 1500PF 300VAC 20% RADIAL; Manufacturer: TDK Corporation; Polarized: N; CompType: Capacitor; Value: 1.5nF; U/M: EA; Cap_F: 0.0000000022; Tolerance_%: 20; Value1: Unknown; VDC_V: 300; Value2: 300V; TempCo: E; TaMin_C: -40; TaMax_C: 125
signal-integrity model Cap
simulation model Cap
footprint E_900x700x900
pins: 1, 2

## EEU-FC1H100
designator C?, comment ValueDisplayed: 10µF  (hidden comment: UVR1H100MDD6TP)
CAP ALUM 10UF 20% 50V RADIAL; Manufacturer: Nichicon; Polarized: Y; CompType: Capacitor; U/M: EA; Cap_F: 0.00001; Tolerance_%: 20; Value1: 2.5 ohm; VDC_V: 50; ESR_ohm: 2.5; IRMS_A: 0.09; TaMin_C: -55; TaMax_C: 105; Cap_Case: 4.0x11.0
signal-integrity model Cap
simulation model Cap
footprint FC_400x1100
pins: 1 +, 2 -

## EEUED2E820S
designator C?, comment ValueDisplayed: 82µF  (hidden comment: UCY2W820MHD6)
CAP ALUM 82UF 20% 450V RADIAL; Polarized: Y; CompType: Capacitor; U/M: EA; Cap_F: 0.000082; Tolerance_%: 20; VDC_V: 450; IRMS_A: 730mA; TaMin_C: -25; TaMax_C: 105; AC_Derating: 0.3
signal-integrity model Cap
simulation model Cap
footprint CAPPR750W80D1600H4000 (Footprint not found)
footprint CAPPRD750W80D1800H3150 (CAPACITOR, POLARIZED, 0.8MM LEAD DIA, PITCH 7.5MM)
pins: 1 +, 2 -

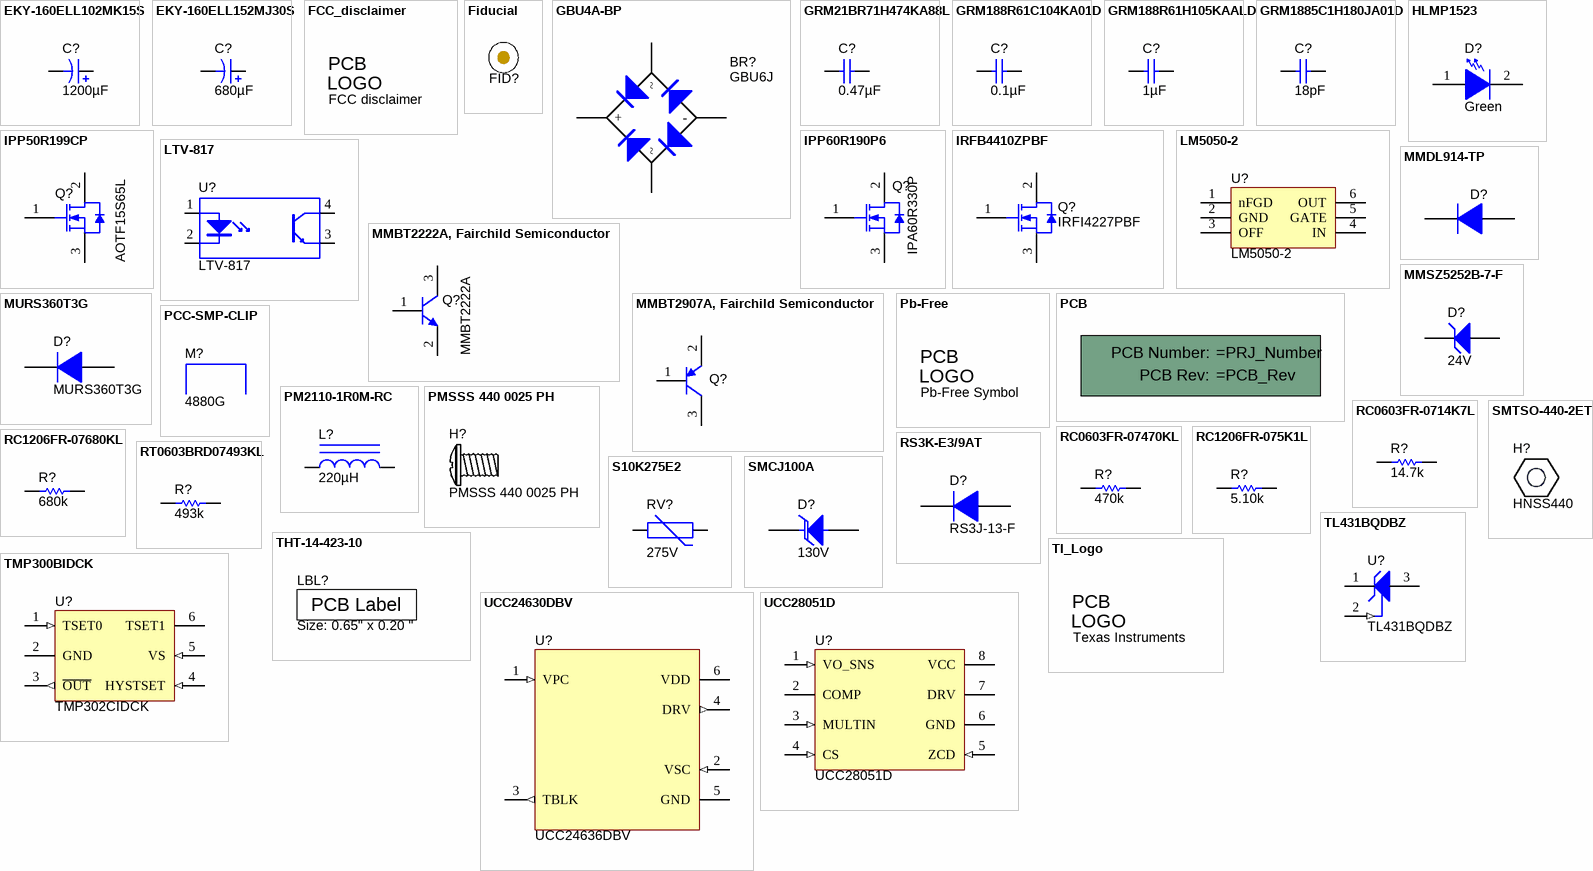
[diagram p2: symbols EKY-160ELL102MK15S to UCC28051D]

## EKY-160ELL102MK15S
designator C?, comment ValueDisplayed: 1200µF  (hidden comment: EKY-350ELL122MK30S)
CAP, AL, 1200 µF, 35 V, +/- 20%, 0.024 ohm, TH; Manufacturer: United Chemi-Con; Polarized: Y; CompType: Capacitor; Value: 1200uF; U/M: EA; Tolerance_%: 20; Value1: 24mOhm; VDC_V: 35; Value2: 35V; ESR_ohm: 24 mOhm; IRMS_A: 2.65A; TaMin_C: -40; TaMax_C: 105; Cap_Case: 12.5x30.0
signal-integrity model Cap
simulation model Cap
footprint KY_1250x1500
footprint CAPPRD500W60D1250H3000 (CAPACITOR, POLARIZED, 0.6MM LEAD DIA, PITCH 5MM)
pins: 1 +, 2 -

## EKY-160ELL152MJ30S
designator C?, comment ValueDisplayed: 680µF  (hidden comment: 680uF)
CAP ALUM 680UF 20% 35V RADIAL; PartNumber: EKY-350ELL681MJ30S; Manufacturer: Chemi-Con; Polarized: Y; CompType: Capacitor; U/M: EA; Cap_F: 0.0015; Tolerance_%: 20; Value1: 0.031 ohm; VDC_V: 35; ESR_ohm: 0.031; IRMS_A: 1.91; TaMin_C: -40; TaMax_C: 105; Cap_Case: 10x30
signal-integrity model Cap
simulation model Cap
footprint KY_1000x3000
footprint CAPPR500W60D1000H3000 (CAPACITOR, POLARIZED, 0.6MM LEAD DIA, PITCH 5MM)
footprint CAPPRD500W60D1000H3000 (CAPACITOR, POLARIZED, 0.6MM LEAD DIA, PITCH 5MM)
pins: 1 +, 2 -

## FCC_disclaimer
designator Logo?, comment FCC disclaimer  (no BOM)
FCC_disclaimer; SymbolCreator: codlsc
footprint FCC_disclaimer
footprint FCC_disclaimer_stacked

## Fiducial
designator FID?  (value not drawn)
Fiducial mark.  There is nothing to buy or mount.; SymbolCreator: codlsc
footprint Fiducial10-30
footprint Fiducial10-20
footprint Fiducial15-30
footprint Fiducial20-40
footprint Fiducial6.4-20

## GBU4A-BP
designator BR?, comment GBU6J
RECT BRIDGE GPP 6A 600V GBU; Manufacturer: Micro Commercial Components; CompType: Diode; U/M: EA; Vf_V: 0.95; Io_A: 4; Vr_V: 50; Value2: 50V; TJmax_C: 150; RJC_CperW: 2.2
footprint GBU (Comchip / Diodes Inc diode bridge)
pins: 1 +, 2 ~, 3 ~, 4 -

## GRM21BR71H474KA88L
designator C?  ValueDisplayed: 0.47µF  (hidden comment: GRM21BR71H474KA88L)
CAP, CERM, 0.47 µF, 50 V, +/- 10%, X7R, 0805; Manufacturer: MuRata; Polarized: N; CompType: Capacitor; Value: 0.47uF; U/M: EA; Cap_F: 0.00000047; Tolerance_%: 10; Value1: Unknown; VDC_V: 50; Value2: 50V; TaMin_C: -55; TaMax_C: 125; Cap_Case: 0805
signal-integrity model Cap
simulation model Cap
footprint 0805_HV
footprint 0805
footprint 0805M
footprint 0805L
pins: 1, 2

## GRM188R61C104KA01D
designator C?  ValueDisplayed: 0.1µF  (hidden comment: GRM188R61C104KA01D)
CAP, CERM, 0.1 µF, 16 V, +/- 10%, X5R, 0603; Manufacturer: MuRata; Polarized: N; CompType: Capacitor; Value: 0.1uF; U/M: EA; Cap_F: 0.0000001; Tolerance_%: 10; Value1: Unknown; VDC_V: 16; Value2: 16V; TaMin_C: -55; TaMax_C: 85; Cap_Case: 0603
signal-integrity model Cap
simulation model Cap
footprint 0603
footprint 0603M
footprint 0603L
footprint 0603_HV
footprint 0603S
pins: 1, 2

## GRM188R61H105KAALD
designator C?  ValueDisplayed: 1µF  (hidden comment: GRM188R61H105KAALD)
CAP, CERM, 1 µF, 50 V, +/- 10%, X5R, 0603; Manufacturer: MuRata; Polarized: N; CompType: Capacitor; Value: 1uF; U/M: EA; Cap_F: 0.000001; Tolerance_%: 10; Value1: Unknown; VDC_V: 50; Value2: 50V; TaMin_C: -55; TaMax_C: 85; Cap_Case: 0603
signal-integrity model Cap
simulation model Cap
footprint 0603
footprint 0603M
footprint 0603L
footprint 0603_HV
footprint 0603S
pins: 1, 2

## GRM1885C1H180JA01D
designator C?  ValueDisplayed: 18pF  (hidden comment: GRM1885C1H180JA01D)
CAP, CERM, 18 pF, 50 V, +/- 5%, C0G/NP0, 0603; Manufacturer: MuRata; Polarized: N; CompType: Capacitor; Value: 18pF; U/M: EA; Cap_F: 0.000000000018; Tolerance_%: 5; Value1: Unknown; VDC_V: 50; Value2: 50V; TaMin_C: -55; TaMax_C: 125; Cap_Case: 0603
signal-integrity model Cap
simulation model Cap
footprint 0603
footprint 0603M
footprint 0603L
footprint 0603_HV
footprint 0603S
pins: 1, 2

## HLMP1523
designator D?, comment value Green  (hidden comment: HLMP1503)
LED SS HI EFF GREEN DIFF 3MM; Manufacturer: Everlight; Vf_V: 2.2; Value2: 2.2V; Io_A: 0.02; Tjmax_C: 100; Value1: W; U/M: EA
signal-integrity model Diode
footprint LED_HLMP1523 (Everlight Electronics)
pins: 1 A, 2 K

## IPP50R199CP
designator Q?, comment AOTF15S65L
MOSFET N-CH 650V 15A TO220F; Manufacturer: Alpha & Omega Semiconductor Inc.; Alternate Manufacturer: None; U/M: EA; ChType: N; VdsMax_V: 650; Value1: 290 mohm; Rdson45_ohm: 0; Value2: 34 nC; QgTyp_nC: 34; Vgs_V: 20
footprint TO-220AB
footprint TO-220AB_HORIZONTAL
footprint TO-220AB_HORIZONTAL_SMT
footprint TO-220AB_100mil
footprint TO-220AB_Horizontal_100mil
footprint TO-220_FullPAK_Offset (Infineon  PG-TO220-3-31)
pins: 1 G, 2 D, 3 S
1 alternate drawing of the same symbol

## IPP60R190P6
designator Q?, comment IPA60R330P
MOSFET N-CH 600V 10.6A TO220; PartNumber: IPA60R330P6XKSA1; Manufacturer: Infineon Technologies; SymbolCreator: x0199378
footprint TO-220AB (Copied from Altium's version of TO3B)
pins: 1 G, 2 D, 3 S

## IRFB4410ZPBF
designator Q?, comment IRFI4227PBF
MOSFET N-CH 200V 26A TO-220FP; Manufacturer: International Rectifier; Alternate Manufacturer: None; U/M: EA; ChType: N; VdsMax_V: 200; Value1: 25 mOhm @ 17A, 10V; Value2: 100 nC; QgTyp_nC: 100nC at 10V; Vgs_V: 20; IdsMax_A: 97
footprint TO-220AB (Copied from Altium's version of TO3B)
footprint TO-220AB_HORIZONTAL
footprint TO-220AB_HORIZONTAL_SMT
footprint TO-220AB_100mil
pins: 1 G, 2 D, 3 S
1 alternate drawing of the same symbol

## LM5050-2
designator U?
HIGH SIDE OR-ING FET CONTROLLER; Manufacturer: Used in BOM report; SymbolVersion: use current date i.e. 2008-05-20; SymbolCreator: Use LDAP id; CompType: Used in some BOM reports.  Useful for finding later.; U/M: EA, IN, or GM
footprint tsop-6 (TSOP, 6-Leads, Body 3.1x1.7mm (max), Pitch 0.95mm, IPC Medium Density)
pins: 1 nFGD, 2 GND, 3 OFF, 4 IN, 5 GATE, 6 OUT

## LTV-817
designator U?
Optocoupler, 5 kV, 50-600% CTR, TH-4; Manufacturer: Lite-On; U/M: EA; CTR_Min: 50% @ 5mA; CTR_Max: 600% @ 5mA; Voltage_Isolation_Vrms: 5000; tr_typ: 4us; tf_typ: 3us
footprint DIP762W60P254L460H350Q4B
pins: 1 A, 2 K, 3 E, 4 C

## MMBT2222A, Fairchild Semiconductor
designator Q?, comment MMBT2222A
Transistor, NPN, 40 V, 0.15 A, SOT-23; Manufacturer: Fairchild Semiconductor; CompType: BJT; PNP: 0; NPN: 1; Vceo_V: 40; Vcesat1_V: 0.3; Value: 40 V; IcRated_A: 0.15; Value1: 0.15 A; HfeMax: 300; TaMin_C: -55; TaMax_C: 150; U/M: EA; AEC Category: Q101
footprint SOT-23
footprint SOT-23M
footprint SOT-23L
pins: 1 B, 2 E, 3 C

## MMBT2907A, Fairchild Semiconductor
designator Q?, comment MMBT4403WT1G  (value not drawn)
Transistor, PNP, 40 V, 0.6 A, SOT-323; Manufacturer: Fairchild Semiconductor; CompType: BJT; PNP: 1; NPN: 0; Vceo_V: 40; Vcesat1_V: 0.75; Value: 40 V; IcRated_A: 0.8; Value1: 0.6 A; HfeMax: 300; TaMin_C: -55; TaMax_C: 150; U/M: EA
footprint SOT-323 (Zetex recommended land pattern.  March 2007)
footprint SOT-23M
footprint SOT-23L
pins: 1 B, 2 E, 3 C

## MMDL914-TP
designator D?  (value not drawn)
Diode, Switching, 100 V, 0.2 A, SOD-323; Manufacturer: Micro Commercial Components; Value: 100V; U/M: EA; Vf_V: 1; Value1: 0.2A; Value2: 1V; Io_A: 0.2; Vr_V: 100; TJmax_C: 150; RJC_CperW: 635
signal-integrity model Diode
footprint sod-323 (NXP recommended land pattern)
pins: 1 K, 2 A

## MMSZ5252B-7-F
designator D?  value 24V  (hidden comment: MMSZ5252B-7-F)
Diode, Zener, 24V, 500mW, SOD-123; Manufacturer: Diodes Inc.; SymbolCreator: a0412235; U/M: EA; Power_W: 0.5; Vz_V: 24; Value1: 0.5W; RJA_CperW: 350
signal-integrity model Diode
footprint SOD-123
pins: 1 K, 2 A

## MURS360T3G
designator D?
Diode, Ultrafast, 600 V, 3 A, SMC; Manufacturer: ON Semiconductor; U/M: EA; Vf_V: 1.25; Value: 600V; Value1: 3A; Value2: 1.25V; Io_A: 3; Vr_V: 600; TJmax_C: 175; RJC_CperW: 11
signal-integrity model Diode
simulation model MURS360T3
footprint SMC (Molded Diode, 2-Leads, Body 6.9x5.8mm, IPC Medium Density, based on OnSemi component dimensions and land patterns)
pins: 1 K, 2 A

## Pb-Free
designator Logo?, comment Pb-Free Symbol  (no BOM)
SymbolCreator: a0412235
footprint Pb-Free_Overlay_Medium
footprint Pb-Free_Overlay_Small

## PCB
designator !PCB?, comment Printed Circuit Board  (value not drawn)  (mechanical)
Manufacturer: Any; SymbolCreator: a0412235; CompType: PCB
1 alternate drawing of the same symbol

## PCC-SMP-CLIP
designator M?, comment 4880G
MOUNTING KIT TO-220; Manufacturer: Aavid Thermalloy; SymbolCreator: Altium; CompType: Hardware

## PM2110-1R0M-RC
designator L?, comment ValueDisplayed: 220µH  (hidden comment: 2116-V-RC)
Inductor, Toroid, 220µH, 2.4 A, 0.120 ohm, TH; Manufacturer: Bourns; Value: 220uH; Ind_H: 220E-6; Imax_A: 2.4; Irms: 2.4A @ 30C rise; DCR_ohm: 0.120; Value2: 2.4A; AEC Category: Q200
signal-integrity model Inductor
simulation model Inductor
footprint PM2110
footprint IND_2118-V-RC (INDUCTOR,2 LEAD,VERTICAL MOUNT,8.382mm PITCH,TH)
pins: 1, 2

## PMSSS 440 0025 PH
designator H?
MACHINE SCREW PAN PHILLIPS 4-40; Manufacturer: B&F Fastener Supply; SymbolCreator: a0412235; CompType: Standoff
footprint B_F_PMSSS4400025PH

## RC0603FR-0714K7L
designator R?  ValueDisplayed: 14.7k  (hidden comment: RC0603FR-0714K7L)
RES, 14.7 k, 1%, 0.1 W, 0603; Manufacturer: Yageo America; CompType: Resistor; Value: 14.7k; Res_ohm: 14700; Value_Code: 14k7; Tolerance_%: 1; Power_W: 0.1; Value2: 0.1W; VDC_V: 150; TempCo: 200 ppm/C; EIA_Code: E96; U/M: EA; AEC Category: Q200
signal-integrity model Resistor
simulation model Resistor
footprint 0603
footprint 0603M
footprint 0603L
footprint 0603_HV
footprint 0603S
pins: 1, 2

## RC0603FR-07470KL
designator R?  ValueDisplayed: 470k  (hidden comment: RC0603FR-07470KL)
RES, 470 k, 1%, 0.1 W, 0603; Manufacturer: Yageo America; CompType: Resistor; Value: 470k; Res_ohm: 470000; Tolerance_%: 1; Power_W: 0.1; Value2: 0.1W; VDC_V: 150; TempCo: 200 ppm/C; U/M: EA
signal-integrity model Resistor
simulation model Resistor
footprint 0603
footprint 0603M
footprint 0603L
footprint 0603_HV
footprint 0603S
pins: 1, 2

## RC1206FR-075K1L
designator R?  ValueDisplayed: 5.10k  (hidden comment: RC1206FR-075K1L)
RES, 5.10 k, 1%, 0.25 W, 1206; Manufacturer: Yageo America; CompType: Resistor; Value: 5.10k; Res_ohm: 5100; Value_Code: 5k10; Tolerance_%: 1; Power_W: 0.25; Value2: 0.25W; VDC_V: 200; TempCo: 100 ppm/C; U/M: EA; AEC Category: Q200
signal-integrity model Resistor
simulation model Resistor
footprint 1206
footprint 1206M
footprint 1206L
pins: 1, 2

## RC1206FR-07680KL
designator R?  ValueDisplayed: 680k  (hidden comment: RC1206FR-07680KL)
RES, 680 k, 1%, 0.25 W, 1206; Manufacturer: Yageo America; Value: 680k; CompType: Resistor; Res_ohm: 680000; Tolerance_%: 1; Power_W: 0.25; Value2: 0.25W; VDC_V: 200; TempCo: 100 ppm/C; U/M: EA
signal-integrity model Resistor
simulation model Resistor
footprint 1206
footprint 1206M
footprint 1206L
pins: 1, 2

## RS3K-E3/9AT
designator D?, comment RS3J-13-F
DIODE GEN PURP 600V 3A SMC; Manufacturer: Diodes Incorporated; U/M: EA; Vf_V: 1.3; Value2: 1.3V; Io_A: 3; Vr_V: 600; TJmax_C: 150; RJC_CperW: 50; Type: Switching
signal-integrity model Diode
footprint SMC (Molded Diode, 2-Leads, Body 6.9x5.8mm, IPC Medium Density, based on OnSemi component dimensions and land patterns)
pins: 1 K, 2 A

## RT0603BRD07493KL
designator R?  ValueDisplayed: 493k  (hidden comment: RT0603BRD07493KL)
RES, 493 k, 0.1%, 0.1 W, 0603; Manufacturer: Yageo America; CompType: Resistor; Value: 493k; Res_ohm: 493000; Tolerance_%: 0.1; Value2: 0.1W; VDC_V: 75; TempCo: 25 ppm/C; EIA_Code: E192; U/M: EA; AEC Category: Q200
signal-integrity model Resistor
simulation model Resistor
footprint 0603
footprint 0603M
footprint 0603L
footprint 0603_HV
footprint 0603S
pins: 1, 2

## S10K275E2
designator RV?  value 275V  (hidden comment: S10K275E2)
Varistor 275V RMS 10MM Radial, TH; Manufacturer: EPCOS Inc; SymbolCreator: a0412235
footprint VAR_S10K275E2 (EPCOS)
pins: 1, 2

## SMCJ100A
designator D?, comment value 130V  (hidden comment: 1.5KE130A)
Diode, TVS, Uni, 130V, 1500 W, TH; Manufacturer: Littelfuse; Power_W: 1500; Vr_V: 130; Value1: 1500W
footprint DO-201AD_Vert (Footprint not found)
pins: 1 K, 2 A

## SMTSO-440-2ET
designator H?, comment HNSS440
HEX NUT 1/4" STN STEEL 4-40; Manufacturer: B&F Fastener Supply; SymbolCreator: a0412235; CompType: Hardware

## THT-14-423-10
designator LBL?, comment Size: 0.65" x 0.20 "
Thermal Transfer Printable Labels, 0.650" W x 0.200" H - 10,000 per roll; Manufacturer: Brady; PartNumber: THT-14-423-10; SymbolCreator: a0412235; CompType: Label
footprint Label_650x200

## TI_Logo
designator Logo?, comment Texas Instruments  (no BOM)
Texas Instrument Corporate Signature; SymbolCreator: a0412235
footprint TI_Stacked_SolderMask_Medium
footprint TI_Stacked_SolderMask_Medium_Vertical
footprint TI_STACKED_OVERLAY_SMALL
footprint TI_Stacked_SolderMask_Small_Vertical
footprint TI_Stacked_Overlay_Medium
footprint TI_Stacked_Overlay_Medium_Vertical
footprint TI_Stacked_Overlay_Small
footprint TI_Stacked_Overlay_Small_Vertical
footprint TI_Horizontal_SolderMask_Small
footprint TI_Horizontal_Overlay_Medium
footprint TI_Horizontal_Overlay_Small
footprint TI_Symbol_SolderMask_Medium
footprint TI_Symbol_SolderMask_Small
footprint TI_Symbol_Overlay_Medium
footprint TI_Symbol_Overlay_Small
footprint TI_Horizontal_SolderMask_Medium

## TL431BQDBZ
designator U?
PRECISION PROGRAMMABLE REFERENCE, DBZ0003A; Alternate Manufacturer: Texas Instruments; SymbolCreator: a0412235; CompType: IC; U/M: EA
footprint DBZ0003A_N
footprint DBZ0003A_M
footprint DBZ0003A_L
pins: 1 CATHODE, 2 REF (in), 3 ANODE

## TMP300BIDCK
designator U?, comment TMP302CIDCK
1.8V, Resistor-Programmable TEMPERATURE SWITCH and ANALOG OUT TEMPERATURE SENSOR, DCK0006A; Alternate Manufacturer: None; Manufacturer: Texas Instruments; SymbolCreator: a0412235; CompType: IC; U/M: EA
footprint DCK0006A_N (SOT23, 6-Leads, Body 2x1.3mm, Pitch 0.65mm, Lead Span 2.1mm, IPC Medium Density)
footprint DCK0006A_M
footprint DCK0006A_L
pins: 1 TSET0 (in), 2 GND (power), 3 ~{OUT} (out), 4 HYSTSET (in), 5 VS (in), 6 TSET1 (power)

## UCC24630DBV
designator U?, comment UCC24636DBV
SYNCRONOUS RECTIFIER CONTROLLER WITH LOW POWER STANDBY, DBV0006A; Manufacturer: Texas Instruments; SymbolCreator: a0411947; CompType: IC; U/M: EA
footprint DBV0006A_N
footprint DBV0006A_M
footprint DBV0006A_L
pins: 1 VPC (in), 2 VSC (in), 3 TBLK (out), 4 DRV (out), 5 GND (power), 6 VDD (power)

## UCC28051D
designator U?
TRANSITION MODE PFC CONTROLLER, D0008A; Alternate Manufacturer: None; Manufacturer: Texas Instruments; SymbolCreator: a0412238; CompType: IC; U/M: EA
footprint D0008A_N (SOIC, 8-Leads, Body 4.9x3.9mm, Pitch 1.27mm, IPC Medium Density)
footprint D0008A_M
footprint D0008A_L
pins: 1 VO_SNS (in), 2 COMP, 3 MULTIN (in), 4 CS (in), 5 ZCD (in), 6 GND (power), 7 DRV (power), 8 VCC (power)

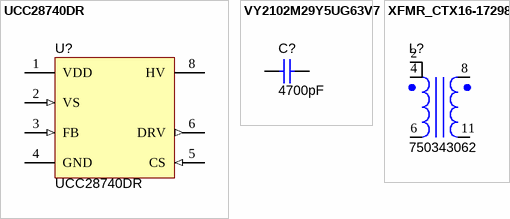
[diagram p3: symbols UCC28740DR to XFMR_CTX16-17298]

## UCC28740DR
designator U?
Constant-Voltage, Constant-Current Flyback Controller Using Opto-Coupler Feedback, D0007A; Manufacturer: Texas Instruments; SymbolCreator: a0412235; CompType: IC; U/M: EA
footprint D0007A_N
footprint D0007A_M
footprint D0007A_L
pins: 1 VDD (power), 2 VS (in), 3 FB (in), 4 GND (power), 5 CS (in), 6 DRV (out), 8 HV (power)

## VY2102M29Y5UG63V7
designator C?, comment ValueDisplayed: 4700pF  (hidden comment: VY2472M49Y5US63V7)
CAP CER 4700PF 440VAC Y5U RADIAL; Manufacturer: Vishay-Bccomponents; Polarized: N; CompType: Capacitor; U/M: EA; Tolerance_%: 20; Value1: Unknown; Value2: 300; TaMin_C: -40; TaMax_C: 125; Cap_Case: Radial Disc 7.5mm, ls=7.5; AEC Category: Q200
signal-integrity model Cap
simulation model Cap
footprint CAPRD750W60D750H1050
pins: 1, 2

## XFMR_CTX16-17298
designator L?, comment 750343062
PFC choke with primary side sensing winding; Manufacturer: Wurth; Value: 330uH
footprint XFMR_CTX16-17298
pins: 2, 4, 6, 8, 11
